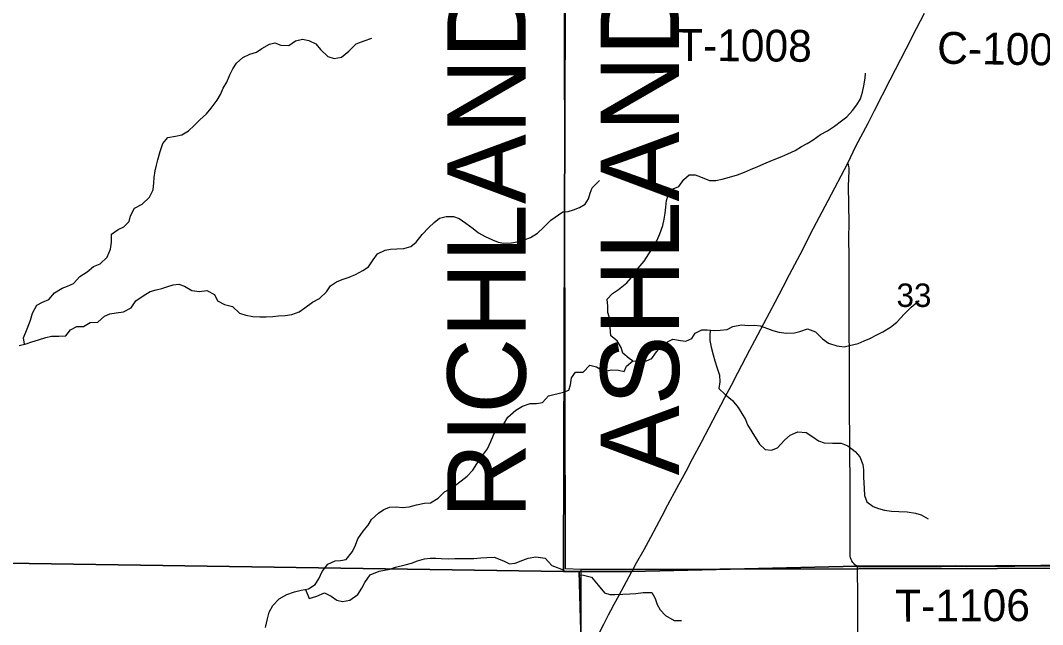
# Model space of a CAD drawing. Extents: x 0 to 70.2, y 0 to 31.4.
# Drawn here: x 5.776 to 7.601, y 18.211 to 19.29 of the extents above; entities that cross this region are included whole.
import ezdxf

# ---------------------------------------------------------------- set-up
doc = ezdxf.new("R2010")
doc.units = 0
for name, color, linetype in [('GM_X_County_Road_Text', 7, 'Continuous'), ('GM_X_Minor_River', 7, 'Continuous'), ('GM_X_Section', 7, 'Continuous'), ('GM_X_Section_Text', 7, 'Continuous'), ('GM_X_State_Route', 7, 'Continuous'), ('GM_X_Township_Road', 7, 'Continuous'), ('GM_X_Township_Road_Text', 7, 'Continuous'), ('SH_Cut_Line', 7, 'Continuous'), ('SH_Text', 7, 'Continuous')]:
    doc.layers.add(name, color=color, linetype=linetype)

msp = doc.modelspace()

# ---------------------------------------------------------------- linework, layer by layer
at = {"layer": 'GM_X_Minor_River'}
for points in [[(5.7832, 18.7116), (5.7819, 18.7228), (5.7884, 18.7394), (5.7942, 18.7546), (5.798, 18.7671), (5.8053, 18.7811), (5.8159, 18.7867), (5.827, 18.7916), (5.8369, 18.8037), (5.8506, 18.8116), (5.8601, 18.8154), (5.8711, 18.8199), (5.8822, 18.8324), (5.8955, 18.841), (5.9069, 18.8505), (5.9187, 18.8553), (5.9313, 18.867), (5.9371, 18.8814), (5.9386, 18.8936), (5.9391, 18.908), (5.9509, 18.9167), (5.9608, 18.9212), (5.9703, 18.931), (5.973, 18.9408), (5.9799, 18.9545), (5.9936, 18.9616), (6.0069, 18.9741), (6.0135, 18.9873), (6.0147, 18.9999), (6.0151, 19.0093), (6.017, 19.0211), (6.019, 19.0313), (6.0217, 19.0412), (6.0259, 19.056), (6.0306, 19.07), (6.0393, 19.0806), (6.0534, 19.0832), (6.0644, 19.0858), (6.0766, 19.0926), (6.0865, 19.102), (6.0968, 19.1122), (6.1082, 19.1231), (6.117, 19.1334), (6.1273, 19.1473), (6.1334, 19.1579), (6.1384, 19.1689), (6.1449, 19.1795), (6.1499, 19.1928), (6.1553, 19.2034), (6.1622, 19.2136), (6.1736, 19.2238), (6.1861, 19.2294), (6.1979, 19.2335), (6.2074, 19.2396), (6.2207, 19.2475), (6.2302, 19.2497), (6.2412, 19.2455), (6.2556, 19.245), (6.2671, 19.2533), (6.28, 19.2563), (6.291, 19.254), (6.3038, 19.2482), (6.3121, 19.2379), (6.325, 19.2257), (6.3367, 19.2222), (6.3496, 19.2245), (6.3626, 19.235), (6.3756, 19.2482), (6.39, 19.2535), (6.4037, 19.2584)], [(6.8691, 18.6817), (6.8635, 18.6863), (6.8518, 18.6954), (6.8487, 18.7057), (6.8419, 18.7174), (6.8305, 18.7265), (6.8294, 18.7421), (6.8298, 18.7527), (6.8253, 18.7683), (6.8253, 18.7793), (6.8241, 18.7922), (6.8332, 18.802), (6.8439, 18.8093), (6.859, 18.8214), (6.8708, 18.8347), (6.8795, 18.8476), (6.8898, 18.8601), (6.8985, 18.873), (6.9046, 18.8832), (6.9129, 18.8965), (6.9182, 18.909), (6.9236, 18.9234), (6.9255, 18.9348), (6.9277, 18.9458), (6.9285, 18.9564), (6.93, 18.9682), (6.9331, 18.9781), (6.9388, 18.9879), (6.952, 18.9932), (6.9608, 19.0057), (6.9706, 19.0141), (6.9812, 19.0141), (6.9907, 19.0106), (7.0067, 19.0038), (7.018, 19.0038), (7.0294, 19.0065), (7.0423, 19.0102), (7.0567, 19.014), (7.0692, 19.019), (7.0799, 19.0239), (7.0931, 19.0292), (7.1079, 19.0356), (7.1223, 19.0413), (7.136, 19.0466), (7.1466, 19.0519), (7.1595, 19.0576), (7.1709, 19.0648), (7.1808, 19.0701), (7.1918, 19.0769), (7.2047, 19.086), (7.2176, 19.0929), (7.2297, 19.1008), (7.2426, 19.1103), (7.2521, 19.1179), (7.262, 19.1289), (7.2699, 19.1391), (7.276, 19.1501), (7.2798, 19.1615), (7.2821, 19.1733), (7.2844, 19.1865), (7.2855, 19.196)], [(6.745, 18.9481), (6.754, 18.9486), (6.7639, 18.9516), (6.7745, 18.9558), (6.7848, 18.9618), (6.7905, 18.9713), (6.7935, 18.9815), (6.7973, 18.991), (6.8102, 19.0043)], [(5.7742, 18.7095), (5.7867, 18.7125), (5.7966, 18.7159), (5.8084, 18.7196), (5.8213, 18.7237), (5.8316, 18.7259), (5.8445, 18.7259), (5.857, 18.7266), (5.8654, 18.7372), (5.8768, 18.7432), (5.889, 18.7431), (5.9008, 18.7507), (5.9144, 18.751), (5.9266, 18.7615), (5.9361, 18.7657), (5.9471, 18.7675), (5.9604, 18.7697), (5.9741, 18.7765), (5.9822, 18.7894), (5.9951, 18.798), (6.008, 18.8055), (6.0183, 18.8085), (6.0285, 18.8111), (6.0392, 18.8149), (6.0491, 18.8175), (6.0593, 18.8186), (6.0692, 18.8155), (6.082, 18.8075), (6.0957, 18.8059), (6.109, 18.8073), (6.123, 18.8004), (6.1282, 18.7894), (6.1407, 18.7825), (6.1551, 18.779), (6.1672, 18.7672), (6.1786, 18.7633), (6.1915, 18.761), (6.2036, 18.7606), (6.215, 18.7605), (6.2271, 18.7612), (6.237, 18.7623), (6.2492, 18.763), (6.2609, 18.7648), (6.2742, 18.7697), (6.2838, 18.7765), (6.2975, 18.7867), (6.31, 18.7934), (6.323, 18.8051), (6.3299, 18.8161), (6.3405, 18.8229), (6.3508, 18.827), (6.3633, 18.8315), (6.3747, 18.836), (6.3877, 18.8432), (6.3976, 18.85), (6.4063, 18.8624), (6.414, 18.873), (6.4273, 18.8798), (6.4372, 18.8813), (6.4482, 18.882), (6.4607, 18.8827), (6.4732, 18.8864), (6.4831, 18.8936), (6.4938, 18.9076), (6.5053, 18.92), (6.5152, 18.9291), (6.5247, 18.9366), (6.5365, 18.94), (6.5498, 18.9399), (6.5596, 18.9361), (6.5717, 18.9281), (6.5846, 18.9181), (6.5944, 18.9105), (6.6061, 18.904), (6.619, 18.8982), (6.6292, 18.894), (6.6395, 18.8924), (6.6531, 18.8927), (6.6634, 18.8946), (6.6744, 18.8972), (6.6869, 18.9025), (6.6995, 18.91), (6.7102, 18.9202), (6.7231, 18.9334), (6.745, 18.9481)], [(6.746, 18.626), (6.7554, 18.6298), (6.7584, 18.6393), (6.76, 18.6515), (6.7675, 18.6617), (6.7812, 18.6617), (6.793, 18.6742), (6.8047, 18.6712), (6.8184, 18.6628), (6.8313, 18.6658), (6.8442, 18.6654), (6.854, 18.6628), (6.8586, 18.6723), (6.8696, 18.6821), (6.8806, 18.681), (6.8942, 18.6817), (6.9037, 18.6863), (6.9102, 18.6958), (6.9178, 18.7052), (6.9314, 18.7159), (6.9409, 18.7204), (6.9546, 18.7181), (6.9644, 18.717), (6.9754, 18.7219), (6.9811, 18.7314), (6.9932, 18.7375), (7.0027, 18.7371), (7.0152, 18.7359), (7.0259, 18.7367), (7.0384, 18.7382), (7.0482, 18.7431), (7.0638, 18.7465), (7.0759, 18.745), (7.0873, 18.7457), (7.0972, 18.7446), (7.1101, 18.7397), (7.1199, 18.7359), (7.1302, 18.7332), (7.1442, 18.7313), (7.1582, 18.732), (7.1677, 18.7343), (7.1814, 18.7389), (7.1961, 18.7339), (7.2083, 18.721), (7.2189, 18.7138), (7.2341, 18.7085), (7.247, 18.707), (7.2568, 18.7092), (7.272, 18.713), (7.283, 18.7179), (7.2932, 18.7217), (7.3069, 18.7289), (7.3164, 18.7339), (7.3296, 18.7422), (7.3414, 18.7509), (7.3551, 18.7657), (7.3668, 18.7778), (7.3809, 18.79)], [(7.008, 18.7366), (7.0073, 18.728), (7.0073, 18.7185), (7.0099, 18.7063), (7.0129, 18.6927), (7.0164, 18.682), (7.0205, 18.6691), (7.0243, 18.6566), (7.0251, 18.6445), (7.0235, 18.6323), (7.0349, 18.6217), (7.0478, 18.6114), (7.0577, 18.5989), (7.0645, 18.5879), (7.0709, 18.5773), (7.0747, 18.5678), (7.0823, 18.5549), (7.0959, 18.5329), (7.1058, 18.5238), (7.1175, 18.5226), (7.1278, 18.5268), (7.1407, 18.5404), (7.1509, 18.5492), (7.1642, 18.5552), (7.179, 18.5541), (7.1911, 18.5465), (7.2014, 18.5389), (7.2116, 18.5358), (7.226, 18.5351), (7.2419, 18.5347), (7.2537, 18.5301), (7.267, 18.5203), (7.2749, 18.5104), (7.2806, 18.4971), (7.2817, 18.4872), (7.2817, 18.474), (7.2821, 18.4641), (7.2829, 18.4538), (7.2836, 18.4417), (7.2878, 18.4299), (7.2988, 18.4216), (7.3083, 18.4182), (7.3192, 18.4155), (7.3318, 18.4136), (7.3447, 18.4128), (7.3598, 18.4121), (7.3746, 18.4098), (7.3845, 18.4067), (7.3974, 18.3999)], [(6.2139, 18.2059), (6.2173, 18.2211), (6.2204, 18.2328), (6.2269, 18.245), (6.2384, 18.2567), (6.2521, 18.2646), (6.2658, 18.2694), (6.2775, 18.2724), (6.2908, 18.2746), (6.3023, 18.2826), (6.3088, 18.2924), (6.3149, 18.306), (6.3252, 18.3189), (6.3381, 18.3249), (6.3476, 18.3252), (6.3579, 18.3271), (6.3693, 18.3414), (6.3743, 18.3528), (6.3785, 18.3642), (6.3885, 18.3778), (6.3969, 18.3884), (6.4034, 18.3986), (6.4156, 18.4099), (6.4251, 18.4167), (6.4353, 18.4205), (6.4475, 18.4212), (6.4577, 18.4203), (6.4706, 18.421), (6.4836, 18.4248), (6.4976, 18.4277), (6.5086, 18.4285), (6.5219, 18.4364), (6.5334, 18.4477), (6.5436, 18.4533), (6.5532, 18.4597), (6.5634, 18.4677), (6.5741, 18.476), (6.584, 18.4865), (6.5913, 18.4979), (6.5993, 18.5104), (6.61, 18.5248), (6.6161, 18.538), (6.6204, 18.5479), (6.6253, 18.5581), (6.6387, 18.5683), (6.6467, 18.5815), (6.6608, 18.5936), (6.6726, 18.6007), (6.6863, 18.6056), (6.698, 18.6059), (6.7083, 18.6078), (6.7194, 18.6195), (6.746, 18.626)], [(6.2854, 18.2737), (6.2919, 18.2576), (6.3056, 18.2617), (6.3189, 18.2677), (6.331, 18.2619), (6.3412, 18.2547), (6.3511, 18.2523), (6.3647, 18.2545), (6.3788, 18.2647), (6.3857, 18.2761), (6.3911, 18.2863), (6.4006, 18.2995), (6.4166, 18.3063), (6.4265, 18.3078), (6.4359, 18.3096), (6.4458, 18.3134), (6.4633, 18.3178), (6.4747, 18.3204), (6.485, 18.3246), (6.4979, 18.3283), (6.5081, 18.3294), (6.518, 18.3293), (6.5275, 18.3289), (6.5408, 18.3285), (6.5522, 18.3288), (6.5616, 18.3291), (6.5753, 18.3287), (6.5859, 18.329), (6.5984, 18.3301), (6.6091, 18.3308), (6.622, 18.3311), (6.639, 18.3246), (6.6496, 18.3196), (6.6595, 18.3207), (6.6732, 18.3259), (6.6831, 18.3293), (6.6967, 18.3319), (6.7134, 18.3295), (6.7251, 18.3166), (6.7471, 18.3078)], [(6.7751, 18.2997), (6.7814, 18.2989), (6.7962, 18.2955), (6.8076, 18.2815), (6.8189, 18.2678), (6.8284, 18.2644), (6.8379, 18.2648), (6.8516, 18.2651), (6.8644, 18.2659), (6.8751, 18.2666), (6.888, 18.2681), (6.9035, 18.2685), (6.9096, 18.2575), (6.9134, 18.2465), (6.9187, 18.237), (6.9281, 18.2271), (6.9437, 18.218), (6.9566, 18.2184)]]:
    msp.add_lwpolyline(points, dxfattribs=at)
at = {"layer": 'GM_X_Section'}
for points in [[(6.7477, 19.3154), (7.76, 19.3074), (7.7683, 18.3114), (6.7772, 18.3092), (6.7496, 18.3103)], [(7.7683, 18.3114), (7.7735, 17.3473), (6.7779, 17.3473), (6.7772, 18.3092)]]:
    msp.add_lwpolyline(points, close=True, dxfattribs=at)
at = {"layer": 'GM_X_Section_Text'}
for points in [[(5.7517, 18.3204), (6.7461, 18.306), (6.749, 19.3206), (6.7395, 20.3365), (6.7343, 20.9), (2.6577, 20.9)], [(8.9, 20.9), (6.7343, 20.9), (6.7395, 20.3365), (6.749, 19.3206), (6.7461, 18.306), (6.7742, 18.3058), (6.8676, 18.3057), (7.2705, 18.3155), (7.2966, 18.3153), (7.3494, 18.3155), (7.3774, 18.3154), (7.4209, 18.3155), (7.4458, 18.3156), (7.4645, 18.3154), (7.5173, 18.3158), (7.5515, 18.3159), (7.5981, 18.3162), (7.6197, 18.3167)], [(6.7786, 18.1369), (6.7742, 18.3058), (6.7461, 18.306), (5.7517, 18.3204)], [(7.6197, 18.3167), (7.5981, 18.3162), (7.5515, 18.3159), (7.5173, 18.3158), (7.4645, 18.3154), (7.4458, 18.3156), (7.4209, 18.3155), (7.3774, 18.3154), (7.3494, 18.3155), (7.2966, 18.3153), (7.2705, 18.3155), (6.8676, 18.3057), (6.7742, 18.3058), (6.7786, 18.1369)]]:
    msp.add_lwpolyline(points, dxfattribs=at)
at = {"layer": 'GM_X_State_Route'}
for points in [[(6.8678, 18.3052), (6.8764, 18.3209), (6.89, 18.3453), (6.9017, 18.3672), (6.9223, 18.4054), (6.9324, 18.4247), (6.9486, 18.4547), (6.9647, 18.4848), (6.9765, 18.5067), (6.9923, 18.5369), (7.0196, 18.5892), (7.034, 18.6167), (7.0457, 18.6386), (7.0573, 18.6605), (7.0789, 18.7018), (7.0875, 18.7183), (7.1036, 18.7484), (7.1139, 18.7676), (7.1241, 18.7867), (7.1383, 18.8142), (7.1497, 18.8363), (7.1684, 18.8721), (7.1925, 18.919), (7.2183, 18.9686), (7.2534, 19.0351), (7.268, 19.0655), (7.2898, 19.1067), (7.3011, 19.1288), (7.3295, 19.1841), (7.358, 19.2394), (7.3763, 19.2754), (7.3903, 19.3031)], [(6.7788, 18.1363), (6.7862, 18.1511), (6.7978, 18.173), (6.8108, 18.1977), (6.8177, 18.2116), (6.8263, 18.2281), (6.8307, 18.2363), (6.8365, 18.2472), (6.8453, 18.2636), (6.8541, 18.28), (6.8675, 18.3046), (6.8678, 18.3052)]]:
    msp.add_lwpolyline(points, dxfattribs=at)
at = {"layer": 'GM_X_Township_Road'}
for points in [[(7.2707, 18.3149), (7.2681, 18.3164), (7.2663, 18.3177), (7.2647, 18.3195), (7.2627, 18.3219), (7.2611, 18.3246), (7.2597, 18.3273), (7.2587, 18.3303), (7.258, 18.3333), (7.2576, 18.3364), (7.2576, 18.3424), (7.2577, 18.3534), (7.2578, 18.38), (7.2578, 18.3984), (7.2576, 18.417), (7.2576, 18.4514), (7.2579, 18.4675), (7.2576, 18.4833), (7.2573, 18.5006), (7.2571, 18.5224), (7.257, 18.5472), (7.2567, 18.5875), (7.2569, 18.6124), (7.2569, 18.6375), (7.2566, 18.6558), (7.2566, 18.6714), (7.2566, 18.6868), (7.2565, 18.7026), (7.2562, 18.724), (7.256, 18.7613), (7.2558, 18.7954), (7.2563, 18.8358), (7.2563, 18.8512), (7.256, 18.8669), (7.2556, 18.9009), (7.2559, 18.9287), (7.2551, 18.994), (7.2558, 19.0211), (7.2558, 19.0265), (7.2557, 19.0291), (7.255, 19.0318), (7.2534, 19.0351)], [(7.2707, 18.3149), (7.2968, 18.3147), (7.3497, 18.3149), (7.3776, 18.3148), (7.4211, 18.3149), (7.446, 18.3151), (7.4647, 18.3149), (7.5175, 18.3152), (7.5517, 18.3154), (7.5983, 18.3156), (7.6199, 18.3161)], [(7.2726, 18.0852), (7.2724, 18.1046), (7.272, 18.1418), (7.2718, 18.1824), (7.2713, 18.2573), (7.2707, 18.3149)]]:
    msp.add_lwpolyline(points, dxfattribs=at)
at = {"layer": 'SH_Cut_Line'}
for points in [[(6.7786, 18.1369), (6.7742, 18.3058), (6.7461, 18.306), (6.749, 19.3206), (6.7395, 20.3365), (6.7343, 20.9), (2.1, 20.9), (2.1, 14.1)], [(8.9, 14.1), (8.9, 20.9), (6.7343, 20.9), (6.7395, 20.3365), (6.749, 19.3206), (6.7461, 18.306), (6.7742, 18.3058), (6.7786, 18.1369)]]:
    msp.add_lwpolyline(points, dxfattribs=at)

# ---------------------------------------------------------------- texts
at = {"layer": 'GM_X_County_Road_Text'}
msp.add_text('C-1008', height=0.05682, rotation=359.0864, dxfattribs=at).set_placement((7.4129, 19.2128))
at = {"layer": 'GM_X_Section_Text'}
msp.add_text('33', height=0.04186, rotation=0, dxfattribs=at).set_placement((7.3406, 18.7782))
at = {"layer": 'GM_X_Township_Road_Text'}
for s, rotation, p in [('T-1008', 359.5283, (6.9484, 19.2179)), ('T-1106', 0.242, (7.3382, 18.2162))]:
    msp.add_text(s, height=0.05682, rotation=rotation, dxfattribs=at).set_placement(p)
at = {"layer": 'SH_Text'}
for s, p in [('RICHLAND COUNTY', (6.6785, 18.4002)), ('ASHLAND COUNTY', (6.9522, 18.4775))]:
    msp.add_text(s, height=0.14, rotation=90, dxfattribs=at).set_placement(p)

doc.saveas('drawing.dxf')
